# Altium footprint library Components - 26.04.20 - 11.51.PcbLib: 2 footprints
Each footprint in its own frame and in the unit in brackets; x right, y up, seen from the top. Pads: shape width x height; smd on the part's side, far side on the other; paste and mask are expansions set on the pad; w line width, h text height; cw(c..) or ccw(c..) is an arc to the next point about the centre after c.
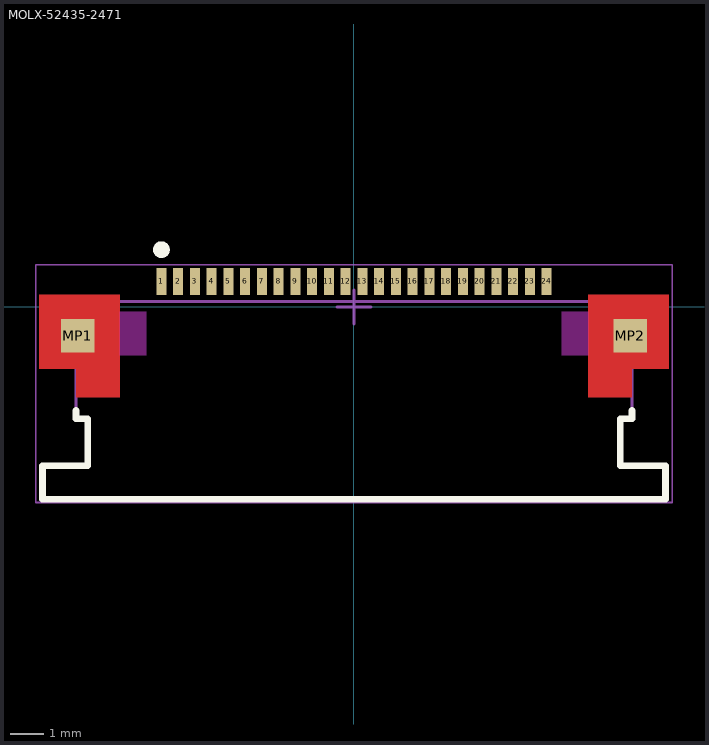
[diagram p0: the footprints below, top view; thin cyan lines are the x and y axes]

## MOLX-52435-2471 [mm] "FPC Connector, 24-Leads, Right Angle, Pitch 0.5 mm, Mated Height 2.0 mm, SMT"
height 2.05
pads (26):
  rect 0.3x0.8 smd: 1(-5.75,0.762) 2(-5.25,0.762) 3(-4.75,0.762) 4(-4.25,0.762) 5(-3.75,0.762) 6(-3.25,0.762) 7(-2.75,0.762) 8(-2.25,0.762) 9(-1.75,0.762) 10(-1.25,0.762) 11(-0.75,0.762) 12(-0.25,0.762) 13(0.25,0.762) 14(0.75,0.762) 15(1.25,0.762) 16(1.75,0.762) 17(2.25,0.762) 18(2.75,0.762) 19(3.25,0.762) 20(3.75,0.762) 21(4.25,0.762) 22(4.75,0.762) 23(5.25,0.762) 24(5.75,0.762)
  rect 1x1 smd: MP1(-8.25,-0.863) MP2(8.25,-0.863)
Top Layer:
  region: 7,0.362 9.4,0.362 9.4,-1.838 8.3,-1.838 8.3,-2.688 7,-2.688
  region: -7,0.362 -9.4,0.362 -9.4,-1.838 -8.3,-1.838 -8.3,-2.688 -7,-2.688
Top Overlay:
  circle w0.25: c-5.75,1.712 r0.125
  lines w0.2: -8.3,-3.338 -7.95,-3.338 -7.95,-4.738 -9.3,-4.738 -9.3,-5.738 ; -8.3,-3.338 -8.3,-3.088 ; 8.3,-3.338 8.3,-3.088 ; 8.3,-3.338 7.95,-3.338 7.95,-4.738 9.3,-4.738 9.3,-5.738 ; -9.3,-5.738 -9.3,-5.738 ; -9.3,-5.738 9.3,-5.738 ; 9.3,-5.738 9.3,-5.738
Keep-Out Layer:
  region: 6.2,-0.137 7,-0.137 7,-1.438 6.2,-1.438
  region: -7,-0.137 -6.2,-0.137 -6.2,-1.438 -7,-1.438
Mechanical 13:
  lines w0.1: -8.3,-3.338 -7.95,-3.338 ; -8.3,-3.338 -8.3,0.162 8.3,0.162 8.3,-3.338 ; -7.95,-3.338 -7.95,-4.738 -9.3,-4.738 -9.3,-5.738 9.3,-5.738 9.3,-4.738 7.95,-4.738 7.95,-3.338 ; 7.95,-3.338 8.3,-3.338
Mechanical 15:
  lines w0.05: -9.5,-5.838 9.5,-5.838 9.5,1.262 -9.5,1.262 -9.5,-5.838
  lines w0.1: -0.5,0 0.5,0 ; 0,-0.5 0,0.5
3D body "524352471.stp": height 2.05, standoff 0, extent -9.3,-5.738 9.3,0.862

## PCBComponent_1 [mm]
